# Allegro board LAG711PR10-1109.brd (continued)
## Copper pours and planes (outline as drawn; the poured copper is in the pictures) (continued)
BST_VCORE1 on BOTTOM (solid shape): 164.5,68.19 164.5,67.56 164.18,67.24 164.18,66.23 164.05,66.1 163.99,66.1 163.86,66.23 163.86,66.86 163.48,67.24 163.48,68.19 163.55,68.26 164.44,68.26
BST_VCORE2 on BOTTOM (solid shape): 168.65,86.51 168.65,85.64 168.6,85.58 167.85,85.58 167.63,85.36 166.65,85.36 166.56,85.45 166.56,85.6 166.65,85.7 167.21,85.7 167.49,85.99 167.49,85.99 168.02,86.51 168.64,86.51
BST_VCORE2_R on BOTTOM (solid shape): 170.13,86.41 170.13,84.44 170.03,84.34 169.61,84.34 169.39,84.34 169.32,84.41 169.32,86.43 169.39,86.5 170.03,86.5
BST_VGT1 on BOTTOM (solid shape): 160.53,96.75 160.53,96.18 160.47,96.12 160.34,96.12 160.02,95.8 160.02,94.97 159.96,94.91 159.7,94.91 159.64,94.97 159.64,95.54 159.64,95.54 159.64,96.75 159.7,96.82 160.47,96.82
BST_VGT1_R on BOTTOM (solid shape): 161.8,98.15 161.8,97.64 161.67,97.51 159.77,97.51 159.64,97.64 159.64,98.15 159.77,98.28 161.67,98.28
DCIN_CHG on BOTTOM (solid shape): 201.04,50.97 201.04,50.67 201.09,50.62 201.63,50.62 201.93,50.33 201.93,50.12 202.01,50.03 202.66,50.03 202.79,49.91 202.79,49.27 202.73,49.21 202.6,49.21 202.47,49.08 202.47,48.64 202.66,48.45 203.11,48.45 203.36,48.19 203.36,47.18 203.3,47.11 203.11,47.11 203.04,47.18 203.04,47.37 201.68,48.73 201.68,49.23 201.39,49.53 200.11,49.53 200,49.64 200,51.05 200.12,51.18 200.83,51.18
DP_VSSR on BOTTOM (solid shape): outline of 330 points within 111.82,130.69 115.88,133.16
DP_VSSR on BOTTOM (solid shape): outline of 741 points within 111.53,134.93 116.37,139.71
DP_VSSR on IN3: 115.54,139.23 116.04,139.23 116.26,139 116.26,136.1 117.28,135.09 117.28,132.09 116.62,131.43 115.93,131.43 115.6,131.1 115.6,130.82 115.4,130.62 113.64,130.62 111.54,132.71 111.54,138.68 112.24,139.38 115.41,139.38 115.54,139.25
LG1_CHG on BOTTOM (solid shape): 195.3,40.06 195.3,39.81 195.17,39.68 193.2,39.68 193.07,39.81 193.07,40.06 193.2,40.19 195.17,40.19
LG1_CHG on BOTTOM (solid shape): 203.04,44.19 203.04,44.06 202.79,43.81 202.79,43.62 202.09,42.92 201.84,42.92 201.71,43.05 201.71,43.43 202.09,43.81 202.09,44.13 202.22,44.25 202.98,44.25
LG1_CHG on IN3 (solid shape): 196,40.06 196,39.56 195.87,39.43 194.53,39.43 194.22,39.75 194.22,40.06 194.34,40.19 195.87,40.19
LG1_CHG on IN3 (solid shape): 202.73,43.62 202.73,43.11 201.84,42.22 201.46,42.22 201.2,42.48 201.2,42.79 202.28,43.87 202.47,43.87
LG1_VGA on TOP (solid shape): 85.49,128.62 85.49,127.83 85.35,127.69 84.29,127.69 84.24,127.74 84.24,128.53 84.24,128.67 84.36,128.8 85.32,128.8
LG1_VGA on TOP (solid shape): 76.74,129.2 77.34,129.2 77.44,129.1 77.45,129.1 78,129.1 78.12,128.97 78.12,128.72 78.04,128.63 77.77,128.63 77.53,128.88 77.39,128.88 77.28,128.99 76.34,128.99 76.28,129.06 76.28,129.14 76.33,129.2 76.74,129.2
LG1_VGA on BOTTOM (solid shape): 90.08,128.47 90.08,127.8 89.96,127.68 89.94,127.68 89.84,127.58 88.92,127.58 88.6,127.9 88.6,128.37 88.91,128.67 89.87,128.67
LG1_VGA on IN3 (solid shape): 89.91,128.54 89.91,127.73 89.78,127.6 83.55,127.6 83.42,127.73 83.42,128.61 83.57,128.76 89.7,128.76
LG2_VGA on TOP (solid shape): 89.89,132.2 89.89,131.29 89.84,131.24 88.86,131.24 88.72,131.38 88.72,132.08 88.91,132.27 89.82,132.27
LG2_VGA on TOP (solid shape): 77.68,130.22 78.02,130.22 78.02,130.22 78.14,130.1 78.14,129.89 78.02,129.77 77.74,129.77 77.42,130.09 77.39,130.09 77.29,130.2 76.34,130.2 76.28,130.26 76.28,130.35 76.34,130.4 77.49,130.4
LG2_VGA on BOTTOM (solid shape): 85.58,132.02 85.58,131.42 85.45,131.29 84.39,131.29 84.31,131.36 84.31,132.23 84.41,132.33 85.28,132.33
LG2_VGA on IN3 (solid shape): 90.1,132.2 90.1,131.39 89.9,131.19 83.5,131.19 83.35,131.34 83.35,132.24 83.5,132.39 89.91,132.39
LG2_VGA on IN3 (solid shape): 79.27,130.25 79.27,129.8 79.17,129.71 77.64,129.71 77.56,129.78 77.56,130.13 77.66,130.22 78.15,130.22 78.15,130.22 78.59,130.22 78.71,130.34 79.17,130.34
LG_1.2V on TOP (solid shape): 38.08,27.32 38.37,27.32 38.38,27.3 38.62,27.3 40.51,25.4 40.86,25.4 40.97,25.29 40.97,24.78 40.67,24.48 40.42,24.48 38.12,26.78 37.63,26.78 37.55,26.86 37.55,27.62 37.6,27.67 37.73,27.67
LG_VCCSA on BOTTOM (solid shape): 161.72,52.64 161.72,51.64 161.58,51.49 160.94,51.49 160.82,51.62 160.82,52.19 161.4,52.77 161.59,52.77
LG_VCCSA on BOTTOM (solid shape): 167.36,52.42 167.36,51.98 166.77,51.39 166.11,51.39 166.01,51.49 166.01,51.99 166.51,52.49 167.29,52.49
LX1_CHG on TOP (solid shape): 191.23,44.32 191.23,42.92 190.98,42.67 189.77,42.67 189.45,42.98 189.45,44.32 189.52,44.38 191.17,44.38
LX1_CHG on BOTTOM (solid shape): 191.17,45.21 191.17,43.37 192.5,42.03 192.5,39.75 192.46,39.71 186.57,39.71 186.47,39.81 186.47,43.37 186.66,43.56 188.06,43.56 188.88,44.38 188.88,44.95 189.26,45.33 191.04,45.33
LX1_CHG on BOTTOM (solid shape): 203.04,44.57 203.04,44.45 202.98,44.38 202.15,44.38 201.96,44.19 201.96,43.94 201.08,43.05 199.65,43.05 199.5,43.2 199.5,43.86 199.7,44.06 201.33,44.06 201.9,44.64 202.98,44.64
LX1_CHG on IN3 (solid shape): 190.69,45.14 190.69,44.57 190.57,44.45 189.04,44.45 188.85,44.64 188.85,45.02 189.04,45.21 190.63,45.21
LX1_CHG on IN3 (solid shape): 201.96,44.25 201.96,43.94 201.14,43.11 200.31,43.11 200.12,43.3 200.12,43.75 200.25,43.87 201.14,43.87 201.65,44.38 201.84,44.38
LX1_VGA on TOP (solid shape): 77.34,128.75 77.47,128.75 77.72,128.5 78.09,128.5 78.09,128.51 78.38,128.51 78.52,128.65 79.03,128.65 79.09,128.58 79.09,128.07 78.96,127.95 77.82,127.95 77.79,127.96 77.66,128.1 77.66,128.3 77.4,128.56 77.34,128.56 77.3,128.6 76.34,128.6 76.28,128.66 76.28,128.75 76.34,128.8 77.29,128.8
LX1_VGA on TOP (solid shape): 97.85,127.21 97.85,126.02 97.32,125.49 94.59,125.49 94.36,125.26 93.98,125.26 93.97,125.24 93.87,125.24 92.57,123.93 90.17,123.93 89.47,124.63 85.16,124.63 85.02,124.77 85.02,127.25 85.12,127.35 92.86,127.35 92.92,127.29 94.77,127.29 94.78,127.29 95.14,127.45 95,127.81 94.97,127.82 94.97,128.71 95.09,128.84 96.22,128.84
LX1_VGA on BOTTOM (solid shape): 97.22,127.34 97.22,125.82 97.07,125.67 95.35,125.67 94.84,126.18 94.64,126.18 93.43,127.39 93.32,127.39 92.78,126.86 92.78,126.7 93.66,125.83 93.66,124.82 92.72,123.88 89.82,123.88 89.06,124.65 85.12,124.65 85.05,124.72 85.05,127.24 85.23,127.41 90.06,127.41 91.39,128.74 92.81,128.74 93.42,129.34 95.22,129.34
LX1_VGA on IN3 (solid shape): 89.73,125.86 89.73,125.14 89.57,124.98 88.65,124.98 88.49,125.14 88.49,125.72 88.65,125.88 89.15,125.88 89.31,126.04 89.55,126.04
LX2_VGA on TOP (solid shape): 78.71,131.57 78.71,131.09 77.96,130.35 77.73,130.35 77.48,130.59 76.35,130.59 76.28,130.66 76.28,130.75 76.34,130.81 77.5,130.81 78.01,131.31 78.01,131.5 78.14,131.63 78.65,131.63
LX2_VGA on TOP (solid shape): 94.62,136.04 94.62,135.62 94.62,135.55 94.62,135.48 94.62,135.35 95.88,134.09 95.88,132.9 95.4,132.42 94.91,132.42 94.74,132.59 92.88,132.59 92.71,132.42 85.24,132.42 85.07,132.58 85.07,135.24 85.28,135.44 89.57,135.44 90.97,136.84 93.82,136.84
LX2_VGA on BOTTOM (solid shape): 94.56,136.08 94.56,135.61 93.85,134.89 93.71,134.89 93,134.18 93,134.04 93.48,133.56 93.66,133.56 94.27,134.17 94.52,134.17 95.22,133.47 95.22,133.28 93.51,131.57 90.85,131.57 89.9,132.52 85.16,132.52 85.09,132.6 85.09,135.31 85.28,135.5 88.67,135.5 88.67,135.51 89.64,135.51 90.98,136.85 93.79,136.85
LX2_VGA on IN3 (solid shape): 79.01,131 79.01,130.86 78.5,130.35 77.68,130.35 77.59,130.45 77.59,130.73 77.75,130.89 78.16,130.89 78.51,131.24 78.77,131.24
LX2_VGA on IN3 (solid shape): 91.5,135.56 91.5,135.24 91.3,135.03 90.85,135.03 90.32,134.5 90.17,134.5 89.84,134.83 89.84,135.11 90.38,135.65 91.4,135.65
LX_1.2V on TOP (solid shape): 49.69,30.16 49.69,28.63 49.63,28.57 46.88,28.57 46.74,28.71 46.74,29.85 47.11,30.22 49.63,30.22
LX_1.2V on TOP (solid shape): 39.12,27.77 40.18,27.77 40.23,27.72 40.23,27.17 40.62,26.79 40.62,26.41 40.48,26.27 39.96,26.27 38.54,27.69 38.16,27.69 37.96,27.9 37.96,28.06 38.01,28.11 38.78,28.11
LX_1.2V on BOTTOM (solid shape): 49.9,29.32 49.9,25.85 49.88,25.84 47.41,25.84 47.28,25.71 46.96,25.71 46.73,25.94 43.83,25.94 43.73,26.04 43.73,26.88 43.82,26.97 46.45,26.97 46.8,27.31 46.8,29.08 47.11,29.4 49.82,29.4
LX_1.05V on TOP (solid shape): 157.77,47.94 157.77,46.29 157.64,46.16 156.12,46.16 155.99,46.29 155.99,47.81 156.24,48.06 157.64,48.06
LX_1.05V on BOTTOM (solid shape): 158.28,48.06 158.38,47.99 158.5,47.96 158.72,47.75 158.72,44.64 159.1,44.26 161.26,44.26 161.39,44.14 161.39,42.67 161.2,42.48 160.69,42.48 160.56,42.35 160.56,41.71 160.44,41.59 159.8,41.59 158.81,42.58 156.2,42.58 155.8,42.98 155.8,47.56 156.31,48.06
LX_1.8V on TOP (solid shape): 199.65,54.48 199.65,53.02 199.46,52.83 198,52.83 197.93,52.89 197.93,54.54 198,54.61 199.52,54.61
LX_1.8V on BOTTOM (solid shape): 201.84,54.99 201.84,54.29 201.77,54.22 200.82,54.22 200.5,53.91 200.5,53.34 199.61,52.45 196.19,52.45 196,52.64 196,54.86 196.19,55.05 201.77,55.05
LX_3V on BOTTOM (solid shape): 28.2,44.74 28.2,42.6 27.57,41.97 25.52,41.97 24.42,40.87 22.18,40.87 20.98,42.07 20.49,42.07 20.48,42.08 18.88,42.08 18.87,42.07 18.85,42.07 18.8,42.04 18.73,41.96 17.91,41.96 17.88,41.99 17.88,42.22 17.98,42.32 18.73,42.32 18.74,42.32 18.76,42.32 18.83,42.4 20.53,42.4 20.54,42.41 20.73,42.41 21.04,42.72 21.87,42.72 21.9,42.76 22.36,43.21 23.4,43.21 23.73,43.54 23.73,44.76 24.11,45.14 27.8,45.14
LX_5V on BOTTOM (solid shape): 22.62,101.91 22.7,101.74 22.85,101.64 23.02,101.47 23.02,101.26 23.02,101.26 23.02,99.02 23.03,99.01 23.03,98.87 23.66,98.24 24.38,98.24 24.47,98.15 26.62,98.15 26.67,98.2 27.58,98.2 27.61,98.17 27.61,97.97 27.53,97.89 26.59,97.89 26.57,97.88 26.51,97.82 24.95,97.82 24.94,97.81 24.85,97.81 24.54,97.49 21.16,97.49 21.04,97.61 17.5,97.61 17.42,97.68 17.42,101.71 17.88,102.17 22.36,102.17
LX_+1.35VGPU on TOP (solid shape): 149.11,110.5 149.11,109.04 148.95,108.89 147.28,108.89 147.2,108.96 147.2,110.57 147.3,110.68 148.93,110.68
LX_+1.35VGPU on BOTTOM (solid shape): 149.09,111.36 149.09,108.16 148.88,107.95 146.82,107.95 146.21,107.34 143.86,107.34 143.73,107.46 143.73,108.48 143.86,108.61 145.63,108.61 146.2,109.17 146.2,111.51 146.34,111.65 148.8,111.65
LX_VCCSA on TOP (solid shape): 160.63,54.61 160.63,53.21 160.44,53.02 158.91,53.02 158.85,53.08 158.85,54.8 158.91,54.86 160.37,54.86
LX_VCCSA on BOTTOM (solid shape): 160.82,55.12 160.82,54.39 161.19,54.02 163.88,54.02 164.33,53.57 167.31,53.57 167.37,53.51 167.37,53.27 167.31,53.21 166.47,53.21 166.32,53.06 165.83,53.06 165.74,53.14 164.29,53.14 164.18,53.03 161.27,53.03 160.21,51.97 158.05,51.97 157.82,52.21 157.82,53.38 158.73,53.38 158.73,54.19 157.82,54.19 157.82,55.35 158.09,55.62 160.31,55.62
LX_VCORE1 on BOTTOM (solid shape): 161.74,63.41 161.74,62.21 161.93,62.02 165.64,62.02 165.69,61.96 165.69,61.26 165.67,61.24 161.71,61.24 160.08,59.62 155.62,59.62 155.01,60.24 155.01,62.53 155.13,62.65 156.34,62.65 156.4,62.59 156.4,61.7 156.47,61.64 157.23,61.64 157.29,61.7 157.29,62.59 158.18,63.48 161.67,63.48
LX_VCORE2 on TOP (solid shape): 158.19,88.79 158.19,87.21 158.09,87.1 155.39,87.1 155.13,87.35 155.13,88.63 155.4,88.89 158.09,88.89
LX_VCORE2 on BOTTOM (solid shape): 159.82,88.62 163.77,88.62 163.9,88.5 163.9,87.86 163.83,87.8 162.56,87.8 162.43,87.67 162.43,83.93 162.31,83.8 160.56,83.8 159.91,84.45 158.54,84.45 158.05,84.94 158.05,87.61 157.99,87.67 157.23,87.67 157.16,87.61 157.16,86.72 157.1,86.66 155.83,86.66 155.13,87.35 155.13,88.62 155.64,89.13 159.31,89.13
LX_VGT1 on TOP (solid shape): 152.62,92.45 152.62,90.8 152.56,90.74 150.4,90.74 150.21,90.93 150.21,92.07 150.66,92.51 152.56,92.51
LX_VGT1 on BOTTOM (solid shape): 156.2,92.31 157.48,92.31 157.55,92.24 157.55,90.97 157.74,90.78 161.46,90.78 161.53,90.72 161.53,90.05 161.32,89.85 155.13,89.85 154.22,90.75 150.49,90.75 150.28,90.97 150.28,92.77 150.66,93.15 152.26,93.15 152.29,93.12 152.29,92.2 153.1,92.2 153.1,93.37 153.39,93.66 154.85,93.66
PHASE_VCORE1 on BOTTOM (solid shape): 165.77,68.56 165.77,67.5 165.2,66.92 165.2,66.16 165.13,66.1 164.88,66.1 164.82,66.16 164.82,66.99 164.75,67.05 164.75,68.19 164.79,68.23 164.79,68.58 164.93,68.73 165.6,68.73
PHASE_VCORE2 on BOTTOM (solid shape): 169.15,85.06 169.15,84.51 168.99,84.35 166.54,84.35 166.49,84.39 166.49,84.67 166.54,84.72 167.44,84.72 167.99,85.27 168.93,85.27
PHASE_VGT1 on BOTTOM (solid shape): 161.74,97.12 161.74,96.57 162.11,96.2 162.11,96.03 161.94,95.86 161.25,95.86 161,95.6 161,95.01 160.91,94.92 160.78,94.92 160.66,95.04 160.66,95.94 160.85,96.13 160.85,97.11 161,97.27 161.59,97.27
QPCN_CHG on BOTTOM (solid shape): 204.14,43.88 204.14,42.79 204.05,42.4 204.38,42.17 204.45,42.14 204.48,42.07 204.48,41.32 204.36,41.2 204.34,41.21 204.24,41.21 204.16,41.18 204.15,41.18 203.82,41.18 203.59,41.41 203.59,42.28 203.82,42.51 203.82,42.77 203.88,42.84 203.88,43.89 203.92,43.92 204.09,43.92
QPCP_CHG on BOTTOM (solid shape): 204.96,43.88 204.96,42.79 204.91,42.61 204.96,42.42 205.02,42.35 205.07,42.3 205.11,42.27 205.15,42.27 205.27,42.25 205.38,42.27 205.42,42.27 205.48,42.21 205.48,41.21 205.46,41.18 204.81,41.18 204.75,41.24 204.75,42.14 204.75,42.15 204.78,42.31 204.73,42.47 204.73,42.56 204.71,42.65 204.71,42.66 204.71,43.9 204.74,43.94 204.91,43.94
REGOUT on TOP (solid shape): 21.08,86.1 22.04,86.1 22.12,86.02 22.13,86.02 22.41,85.74 22.41,84.98 22.64,84.75 22.83,84.75 22.9,84.68 22.9,83.97 22.83,83.9 22.66,83.9 22.59,83.97 21.28,83.97 21.13,84.12 21.13,84.14 21.02,84.4 20.77,84.5 20.75,84.5 20.7,84.55 20.7,84.57 20.59,84.82 20.35,84.92 20.33,84.92 20.05,85.2 20.06,85.23 20.09,85.32 20.1,85.41 20.06,85.56 19.96,85.67 19.96,85.99 20.11,86.14 21.04,86.14
RING2 on TOP (solid shape): 33.03,17.1 33.03,16.34 32.77,16.09 32.77,15.17 32.72,15.12 32.6,15.12 32.55,15.17 32.55,17.13 32.62,17.2 32.93,17.2
RING2 on TOP (solid shape): 21.31,15.36 21.94,15.36 22,15.3 22,14.54 21.94,14.47 20.1,14.47 20.04,14.54 20.04,15.24 20.16,15.36 20.73,15.36 20.87,15.5 21.17,15.5
RING2 on BOTTOM (solid shape): 22.45,14.79 22,14.35 20.92,14.35 20.73,14.54 20.73,15.3 20.92,15.49 21.69,15.49 21.94,15.74 22.45,15.74
RING2 on BOTTOM (solid shape): 33.12,18.09 33.12,16.31 32.99,16.19 32.61,16.19 32.55,16.25 32.55,17.2 32.35,17.39 32.23,17.39 32.23,18.41 32.8,18.41
RING2_R on TOP (solid shape): 23.27,18.22 23.27,15.99 23.25,15.96 23.24,15.94 23.24,15.92 23.22,15.83 23.24,15.75 23.24,14.75 23.08,14.6 22.32,14.6 22.32,17.14 21.88,17.58 21.18,17.58 20.92,17.84 20.92,18.98 21.12,19.17 22.32,19.17
RING2_R on IN1 (solid shape): 21.5,18.79 21.5,17.9 20.54,16.95 20.16,16.95 19.91,17.2 19.91,17.71 20.48,18.28 20.48,18.79 20.67,18.98 21.31,18.98
RTCRST_ON on TOP (solid shape): 64,34.01 64,32.48 63.65,32.13 60.49,32.13 60.23,32.38 60.23,32.89 60.16,32.96 60.16,32.99 60.13,32.99 60.04,33.08 59.53,33.08 59.41,33.21 59.41,33.59 59.53,33.71 62.39,33.71 62.96,34.29 63.72,34.29
RTCRST_ON_R on TOP (solid shape): 61.06,36.76 61.06,35.75 61.31,35.49 62.07,35.49 62.2,35.36 62.2,34.79 61.38,33.97 60.42,33.97 60.3,34.09 60.3,36 60.17,36.13 60.17,36.83 60.3,36.95 60.87,36.95
SIO_SLP_S4# on TOP (solid shape): 73.65,110.09 73.65,109.58 73.58,109.5 73.07,109.5 72.95,109.52 72.83,109.5 72.79,109.5 72.77,109.48 72.7,109.42 72.64,109.35 72.63,109.34 72.63,109.32 72.59,109.17 72.63,109.01 72.63,108.93 72.73,108.82 72.86,108.82 72.92,108.81 72.98,108.81 73.04,108.75 73.04,107.95 72.96,107.87 71.92,107.87 71.82,107.97 71.82,109.66 71.94,109.78 72.26,109.78 72.63,110.15 73.6,110.15
SLEEVE on TOP (solid shape): 18.77,15.11 18.77,13.71 18.7,13.65 17.81,13.65 17.62,13.84 17.62,15.04 17.75,15.17 18.7,15.17
SLEEVE on IN1 (solid shape): 19.15,14.98 19.15,13.97 19.08,13.9 17.75,13.9 17.62,14.03 17.62,14.92 17.75,15.04 19.08,15.04
SLEEVE on IN1 (solid shape): 32.42,17.58 32.42,17.03 32.42,17 32.42,16.97 32.42,16.45 32.42,16.42 32.42,16.38 32.42,16.31 32.29,16.19 31.78,16.19 31.66,16.31 31.66,16.76 31.4,17.01 31.21,17.01 31.21,18.03 31.97,18.03
SLEEVE_R on TOP (solid shape): 20.61,18.98 20.61,17.78 19.91,17.08 19.91,14.73 19.78,14.6 19.08,14.6 18.96,14.73 18.96,18.98 19.15,19.17 20.42,19.17
SLEEVE_R on IN1 (solid shape): 19.66,18.85 19.66,17.9 18.64,16.89 18.26,16.89 17.94,17.2 17.94,17.65 18.7,18.41 18.7,18.79 18.89,18.98 19.53,18.98
SN_1.2V on TOP (solid shape): 52.25,30.23 52.25,27.67 52.23,27.65 51.7,27.65 51.66,27.69 51.66,28.35 51.49,28.52 51.25,28.52 51.19,28.58 51.19,30.24 51.21,30.26 52.22,30.26
SN_3V on TOP (solid shape): 24.52,44.61 24.52,43.04 24.43,42.95 23.53,42.95 23.48,43 23.48,43.92 23.32,44.08 22.24,44.08 22.2,44.13 22.2,44.71 22.23,44.75 24.38,44.75
SN_5V on TOP (solid shape): 21.62,102.63 21.62,100.69 21.5,100.56 18.68,100.56 18.62,100.62 18.62,101.36 18.78,101.51 19.55,101.51 19.87,101.84 19.87,102.61 19.93,102.67 21.57,102.67
SNUB_+1.35VGPU on TOP (solid shape): 151.01,111.34 151.01,108.96 150.97,108.92 150.01,108.92 149.87,109.06 149.87,110.4 149.34,110.93 149.34,111.56 149.36,111.59 150.76,111.59
UG1_CHG on BOTTOM (solid shape): 191.17,45.97 191.17,45.65 191.04,45.52 189.01,45.52 188.88,45.65 188.88,45.97 189.01,46.1 191.04,46.1
UG1_CHG on BOTTOM (solid shape): 203.04,45.02 203.04,44.89 202.98,44.83 201.84,44.83 201.2,44.19 200.95,44.19 200.82,44.32 200.82,44.57 201.32,45.07 201.43,45.05 201.54,45.08 202.98,45.08
UG1_CHG on IN3 (solid shape): 190.85,46.16 190.85,45.65 190.72,45.52 189.01,45.52 188.88,45.65 188.88,46.16 189.01,46.29 190.72,46.29
UG1_CHG on IN3 (solid shape): 201.77,44.95 201.77,44.76 201.14,44.13 200.06,44.13 199.87,44.32 199.87,44.7 200.06,44.89 200.95,44.89 201.14,45.08 201.65,45.08
UG1_VGA on TOP (solid shape): 85.52,122.78 85.52,122.22 85.36,122.06 85.05,122.06 84.72,122.4 83.97,122.4 83.8,122.56 83.8,123.22 83.88,123.3 85,123.3
UG1_VGA on TOP (solid shape): 77.53,128.24 77.53,128.05 77.75,127.82 77.8,127.82 77.89,127.73 77.89,127.51 77.78,127.4 77.53,127.4 77.34,127.59 77.34,128.01 77.15,128.2 76.34,128.2 76.28,128.26 76.28,128.35 76.33,128.41 77.36,128.41
UG1_VGA on BOTTOM (solid shape): 90.61,123.02 90.61,122.47 90.49,122.35 89.41,122.35 89.12,122.06 88.79,122.06 88.64,122.21 88.64,122.77 89.02,123.15 90.48,123.15
UG1_VGA on IN3 (solid shape): 90.53,123.43 90.53,122.74 90.41,122.61 89.49,122.61 89.33,122.78 89.33,123.67 89.54,123.88 90.08,123.88
UG1_VGA on IN3 (solid shape): 86.04,123.4 86.04,123.19 85.24,122.39 83.25,122.39 83,122.64 83,122.88 83.4,123.27 85.09,123.27 85.42,123.6 85.84,123.6
UG1_VGA on IN3 (solid shape): 77.74,127.81 77.82,127.81 78.39,127.24 78.39,126.88 78.14,126.63 77.82,126.63 77.57,126.87 77.57,127.29 77.42,127.44 77.42,127.72 77.56,127.86 77.7,127.86
UG2_VGA on TOP (solid shape): 90.05,137.93 90.05,136.69 89.91,136.55 88.79,136.55 88.69,136.64 88.69,137.88 88.91,138.1 89.89,138.1
UG2_VGA on TOP (solid shape): 77.8,131.81 77.8,131.53 77.8,131.37 77.43,131 76.34,131 76.28,131.06 76.28,131.14 76.35,131.2 77.14,131.2 77.33,131.39 77.33,131.8 77.46,131.93 77.68,131.93
UG2_VGA on BOTTOM (solid shape): 85.56,137.71 85.56,136.86 85.43,136.74 84.25,136.74 84.04,136.94 84.04,137.74 84.2,137.89 85.38,137.89
UG2_VGA on IN3 (solid shape): 89.99,137.52 89.99,136.63 89.85,136.49 83.4,136.49 83.23,136.66 83.23,137.59 83.46,137.82 89.69,137.82
UG_1.2V on IN1 (solid shape): 39.35,28.52 39.35,28.51 39.37,28.48 39.45,28.32 39.57,28.17 39.57,27.94 39.44,27.81 38.55,27.81 38.3,28.06 38.3,28.56 38.46,28.72 39.15,28.72
UG_VCCSA on BOTTOM (solid shape): 161.72,55.97 161.72,55.28 161.59,55.14 161.1,55.14 160.5,55.74 160.5,56.04 160.66,56.19 161.5,56.19
UG_VCCSA on IN1 (solid shape): 161.72,56.43 161.72,55.28 161.59,55.14 160.72,55.14 160.53,55.33 160.53,56.42 160.69,56.57 161.58,56.57
VCREF0 on TOP (solid shape): 47.07,68.63 47.07,66.79 47.58,66.28 48.04,66.28 48.71,65.6 48.71,65.17 48.66,65.11 47.23,65.11 47.14,65.2 47.14,66.02 47.14,66.03 47.17,66.3 47,66.51 46.85,66.66 46.85,68.6 46.92,68.67 47.03,68.67
N17283936 on TOP (solid shape): 38.98,22.4 38.98,21.54 39.68,20.84 39.68,20.25 39.43,20 38.39,20 37.66,20.72 37.66,22.34 37.75,22.43 38.96,22.43
N17415515 on TOP (solid shape): 73.78,145.5 73.78,144.98 74.29,144.98 74.29,145.48 74.3,145.5 74.56,145.5 74.58,145.48 74.58,144.98 75.69,144.98 75.81,144.85 75.81,141.79 75.59,141.56 72.29,141.56 72.12,141.73 72.12,142.74 72.12,142.8 72.12,144.87 72.23,144.98 73.49,144.98 73.49,144.98 73.49,145.47 73.53,145.51 73.77,145.51
N17415515 on BOTTOM (solid shape): 77.95,146.08 77.95,141.51 77.53,141.09 72.54,141.09 71.96,141.67 71.96,141.97 71.96,141.98 72.08,142.38 72.12,142.8 72.12,146.23 72.45,146.55 77.48,146.55
N19964609 on TOP (solid shape): 98.74,61.72 99.32,61.72 99.37,61.68 99.37,60.72 99.25,60.6 97.72,60.6 97.64,60.68 97.64,62.24 97.67,62.28 98.18,62.28
N20135251 on TOP (solid shape): 73.52,133.9 73.52,133.41 74.08,132.85 74.08,131.86 74.01,131.8 73.15,131.8 73.06,131.88 73.06,132.95 72.84,133.17 72.84,133.89 72.93,133.98 73.44,133.98
N20135264 on TOP (solid shape): 75.08,133.99 75.08,133.47 75.1,133.45 75.1,133.36 75.19,133.36 75.66,132.89 75.66,131.88 75.6,131.82 75.15,131.82 75.09,131.88 75.09,132.61 74.98,132.72 74.98,132.74 74.41,133.32 74.41,133.97 74.49,134.06 75.01,134.06
N21269026 on TOP (solid shape): 161.77,88.73 161.77,87.26 161.61,87.1 159.72,87.1 159.63,87.19 159.63,88.78 159.73,88.88 161.62,88.88
N21273981 on TOP (solid shape): 155.39,92.46 155.39,91.48 155.55,91.32 156.52,91.32 156.64,91.2 156.64,90.44 156.44,90.24 154.72,90.24 154.21,90.76 154.21,92.44 154.36,92.58 155.26,92.58
N21379353 on BOTTOM (solid shape): 24.5,96.74 24.5,96.23 24.26,95.99 24.26,95.64 24.13,95.51 23.83,95.51 23.72,95.62 23.72,95.84 23.53,96.03 23.53,96.78 23.62,96.86 24.37,96.86
N24550044 on TOP (solid shape): 92.79,128.57 92.79,127.73 92.71,127.64 90.17,127.64 90.09,127.72 90.09,128.6 90.18,128.68 92.68,128.68
N24550059 on TOP (solid shape): 80.17,128.39 80.17,126.8 80.11,126.74 79.47,126.74 79.41,126.8 79.41,128.65 79.92,128.65
N24550140 on TOP (solid shape): 92.79,132.16 92.79,131.3 92.72,131.22 90.12,131.22 90.09,131.25 90.09,132.27 90.11,132.29 92.67,132.29
N24550153 on TOP (solid shape): 78.9,134.17 78.9,132.14 78.77,132.01 78.11,132.01 78.08,132.04 78.08,132.63 78.13,132.67 78.13,133.35 78.14,133.35 78.14,134.23 78.18,134.27 78.8,134.27
N28160180 on BOTTOM (solid shape): 31.13,129.07 31.13,126.99 31.02,126.89 30.33,126.89 30.27,126.94 30.27,127.54 29.8,128.02 29.8,129.03 29.98,129.21 30.99,129.21
N28484391 on TOP (solid shape): 169.08,34.37 171.54,34.37 171.58,34.33 171.58,33.8 171.43,33.65 168.83,33.65 168.59,33.89 168.59,34.39 168.68,34.48 168.98,34.48
N28484395 on TOP (solid shape): 170.6,36 170.6,34.65 170.49,34.54 169.59,34.54 169.52,34.61 168.58,34.61 168.46,34.48 168.46,33.86 168.35,33.76 168.02,33.76 167.94,33.84 167.94,34.8 168.26,35.11 169.47,35.11 169.71,35.35 169.71,35.97 169.88,36.15 170.46,36.15
N29179188 on TOP (solid shape): 192.5,58.86 192.5,56.45 191.68,55.62 191.68,53.97 191.04,53.34 187.99,53.34 187.74,53.59 187.74,54.61 187.93,54.8 189.45,54.8 190.03,55.37 190.03,58.92 190.22,59.11 192.25,59.11
N29179461 on TOP (solid shape): 194.34,54.99 194.34,51.94 191.04,48.64 191.04,48.13 190.92,48 186.53,48 186.41,48.13 186.41,52.51 186.53,52.64 191.23,52.64 191.99,53.4 191.99,55.11 192.38,55.49 193.84,55.49
N29179461 on BOTTOM (solid shape): 193.87,55.65 193.87,53.3 193.71,53.14 191.3,53.14 191.3,53.84 191.04,54.1 190.79,54.1 190.53,53.84 190.53,53.14 187.74,53.14 187.61,53.27 187.61,55.94 187.8,56.13 193.39,56.13
N45789065 on TOP (solid shape): 160.18,63.05 160.18,60.51 160.05,60.38 159.04,60.38 158.91,60.51 158.91,62.92 159.17,63.18 160.05,63.18

Small or netless copper shapes (teardrops, artwork), in the pictures only: 320 on TOP, 30 on BOTTOM, 2 on IN1, 54 on IN2, 3 on IN3

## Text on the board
Ref Des/Silkscreen Bottom: H8 | H12
User.Comments: LAG711P | 2018-11-05 | 2019-11-05 | Minjia | EDI73
User.39: trace Width | Width/space | L1-TOP | L2-GND1 | L3-IN1 | L4-VCC | L5-IN2 | L6-IN3 | L7-GND2 | L8-BOT | 5.5mil | 5.8mil | 4.9mil | 4.4mil | 4.7mll | 5.3mil | 4.8 / 3.9 | 5.1 / 3.5 | 4.4 / 4.3 | 4.7 / 3.9 | 5.3 / 4.2 | 3.5 / 6.4 | L2/L4 | L4/L7 | L2 | L7 | 5.6mil | 4.6mil | 5.2/3.5 | 4.6/3.7 | L5/L7 | 1_0mm-8L_170405 | LAYER | NAME | STACKUP: 8 LAYER | 45 ohm | 50 ohm | THICKNESS=1.0mm | 80 ohm | 85 ohm | 100 ohm | Ref
User.40: FIGURE | SIZE | 8.0 | 22.0 | 28.0 | 35.0 | 118.0 | 126.0 | 130.0 | 138.0 | 154.0 | 197.0 | 43.0 | 63.0 | 220.0 | 51.0x28.0 | 55.0x24.0 | 63.0x24.0 | 63.0x35.0 | 67.0x28.0 | 71.0x31.0 | 75.0x28.0 | 102.0x31.0 | 157.0x118.0 | 33.0x28.0 | DRILL CHART: TOP to BOTTOM | ALL UNITS ARE IN MILS | TOLERANCE | +3.0/-3.0 | +2.0/-2.0 | PLATED | NON-PLATED | QTY | 5898 | 19 | 18 | 8 | 5 | 2 | 1 | 4 | 7
User.41: STACK-UP SETTING OK
